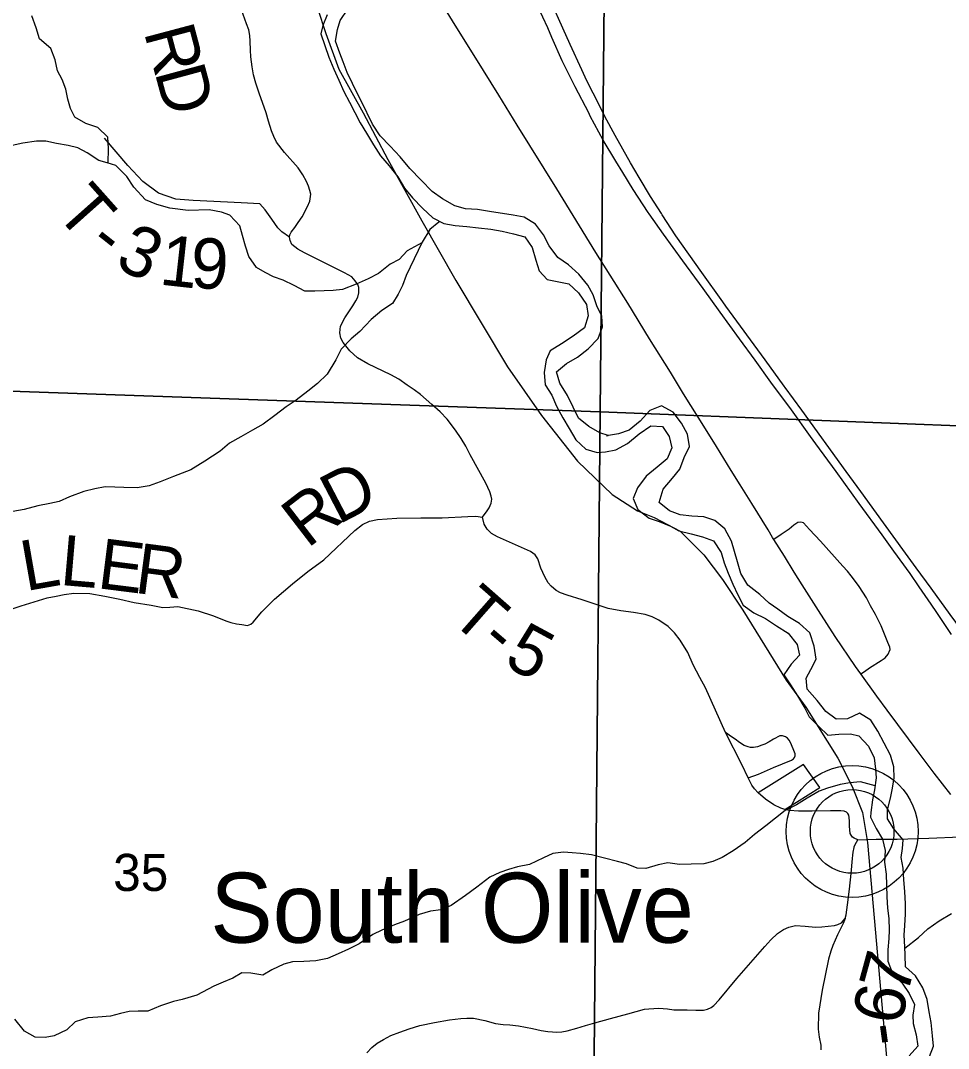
# Model space of a CAD drawing. Extents: x 0 to 34, y 0 to 22.
# Drawn here: x 2.91 to 3.957, y 19.001 to 20.162 of the extents above; entities that cross this region are included whole.
import ezdxf

# ---------------------------------------------------------------- set-up
doc = ezdxf.new("R2010")
doc.units = 0
for name, color, linetype in [('GM_X_County_Road', 7, 'Continuous'), ('GM_X_Interstate_Route', 7, 'Continuous'), ('GM_X_Major_River', 7, 'Continuous'), ('GM_X_Minor_River', 7, 'Continuous'), ('GM_X_Rail_Line', 7, 'Continuous'), ('GM_X_Section', 7, 'Continuous'), ('GM_X_Section_Text', 7, 'Continuous'), ('GM_X_State_Route', 7, 'Continuous'), ('GM_X_Township_Road', 7, 'Continuous'), ('GM_X_Township_Road_Text', 7, 'Continuous'), ('GM_X_Unincorporated', 7, 'Continuous'), ('GM_X_Unincorporated_Location', 7, 'Continuous'), ('GM_X_Unincorporated_Text', 7, 'Continuous')]:
    doc.layers.add(name, color=color, linetype=linetype)

msp = doc.modelspace()

# ---------------------------------------------------------------- linework, layer by layer
at = {"layer": 'GM_X_County_Road'}
msp.add_lwpolyline([(3.8547, 19.2369), (3.8754, 19.2377), (3.899, 19.2377), (3.9348, 19.2389), (3.9706, 19.2404), (3.9804, 19.2423), (3.9864, 19.2446), (3.9913, 19.2477)], dxfattribs=at)
at = {"layer": 'GM_X_Interstate_Route'}
for points in [[(3.634, 19.9423), (3.6329, 19.944), (3.6207, 19.9631), (3.6078, 19.9846), (3.5982, 20.0009), (3.5807, 20.0317), (3.5692, 20.0532), (3.5629, 20.0658), (3.5488, 20.0937), (3.5432, 20.1059), (3.5299, 20.1347), (3.5004, 20.2012)], [(3.6193, 19.9434), (3.6181, 19.945), (3.6011, 19.971), (3.5893, 19.9901), (3.5815, 20.003), (3.5674, 20.0265), (3.5527, 20.0537), (3.551, 20.0573), (3.5355, 20.0866), (3.5292, 20.0994), (3.5209, 20.1162), (3.5092, 20.1424), (3.5047, 20.1532), (3.4936, 20.1773)], [(3.9238, 19.5226), (3.9136, 19.5374), (3.8952, 19.5626), (3.882, 19.5811), (3.8561, 19.6167), (3.8301, 19.6525), (3.8074, 19.6839), (3.8013, 19.692), (3.7797, 19.7221), (3.7566, 19.7535), (3.7387, 19.7782), (3.7212, 19.8022), (3.6992, 19.8324), (3.68, 19.859), (3.657, 19.8905), (3.6354, 19.9204), (3.6193, 19.9434)], [(3.7022, 19.8441), (3.6785, 19.8771), (3.6494, 19.9188), (3.634, 19.9423)], [(3.7727, 19.7474), (3.7715, 19.749), (3.7499, 19.7786), (3.7057, 19.8393), (3.7022, 19.8441)], [(3.9374, 19.5209), (3.9206, 19.5438), (3.9056, 19.5646), (3.8758, 19.6055), (3.858, 19.6299), (3.8416, 19.6525), (3.7913, 19.7217), (3.7727, 19.7474)], [(3.9603, 19.4687), (3.9439, 19.4935), (3.9374, 19.5029), (3.9238, 19.5226)], [(4.4136, 19.002), (4.4082, 19.0064), (4.3656, 19.0403), (4.3133, 19.0822), (4.2605, 19.1242), (4.2222, 19.1561), (4.2043, 19.1721), (4.1931, 19.1833), (4.1764, 19.2002), (4.1626, 19.2155), (4.1424, 19.2399), (4.1299, 19.2562), (4.115, 19.2766), (4.0958, 19.3028), (4.085, 19.318), (4.0563, 19.3574), (4.0431, 19.3754), (4.0122, 19.4179), (3.9866, 19.4532), (3.9769, 19.4666), (3.9589, 19.4914), (3.9374, 19.5209)]]:
    msp.add_lwpolyline(points, dxfattribs=at)
at = {"layer": 'GM_X_Major_River'}
for points in [[(3.5728, 19.6934), (3.5633, 19.6963), (3.551, 19.7034), (3.5392, 19.7128), (3.5333, 19.7252), (3.5271, 19.7384), (3.5182, 19.7524), (3.5146, 19.7652), (3.5259, 19.7745), (3.5384, 19.7818), (3.5504, 19.7911), (3.5617, 19.8029), (3.5664, 19.8159), (3.5659, 19.828), (3.5601, 19.8397), (3.5558, 19.8522), (3.5499, 19.8631), (3.5399, 19.8755), (3.528, 19.8857), (3.5162, 19.8942), (3.5062, 19.9074), (3.4999, 19.9199), (3.4907, 19.9319), (3.4781, 19.9397), (3.4655, 19.9418), (3.4389, 19.9461), (3.4252, 19.9482), (3.4119, 19.9492), (3.3997, 19.9525), (3.3859, 19.9603), (3.3741, 19.9688), (3.3618, 19.9816), (3.3491, 19.9947), (3.3379, 20.0079), (3.3268, 20.0199), (3.3156, 20.0315), (3.3067, 20.0447), (3.2943, 20.0704), (3.2892, 20.0802), (3.2842, 20.0904), (3.2784, 20.1028), (3.2737, 20.1149), (3.2701, 20.1247), (3.265, 20.1383), (3.2672, 20.1516), (3.2705, 20.1616), (3.279, 20.1746)], [(3.2556, 20.1682), (3.2508, 20.156), (3.2486, 20.1465), (3.2576, 20.1204), (3.2631, 20.1068), (3.269, 20.0944), (3.2744, 20.0815), (3.281, 20.0695), (3.2931, 20.0461), (3.3, 20.0344), (3.3078, 20.0212), (3.3159, 20.0088), (3.3255, 19.9975), (3.3355, 19.9851), (3.3429, 19.9723), (3.3521, 19.9614), (3.3633, 19.9497), (3.3748, 19.9389), (3.3874, 19.9326), (3.4003, 19.9301), (3.4133, 19.9291), (3.4266, 19.9277), (3.4403, 19.926), (3.4532, 19.9239), (3.4661, 19.921), (3.4787, 19.9173), (3.4872, 19.9053), (3.4912, 19.8913), (3.4951, 19.8792), (3.5039, 19.8694), (3.5283, 19.8644), (3.5394, 19.8543), (3.5483, 19.8411), (3.5504, 19.8282), (3.5463, 19.8149), (3.5332, 19.8053), (3.5203, 19.7968), (3.5075, 19.7887), (3.5027, 19.7787), (3.5006, 19.7643), (3.5019, 19.7506), (3.5092, 19.7386), (3.5147, 19.7265), (3.5217, 19.7133), (3.5287, 19.7013), (3.5364, 19.6884), (3.5475, 19.678), (3.5605, 19.6739), (3.57, 19.6748), (3.5817, 19.6772), (3.5945, 19.6842), (3.6077, 19.695), (3.6209, 19.7042), (3.6342, 19.7033), (3.6419, 19.692), (3.6447, 19.6795), (3.6396, 19.6669), (3.6283, 19.6577), (3.6159, 19.6473), (3.6058, 19.6342), (3.601, 19.622), (3.6064, 19.6096), (3.6191, 19.5999)], [(3.9355, 18.9924), (3.94, 19.0042), (3.9391, 19.0156), (3.9374, 19.0308), (3.9353, 19.0429), (3.9329, 19.0569), (3.9282, 19.0697), (3.9197, 19.0833), (3.9086, 19.0934), (3.908, 19.1067), (3.9079, 19.1162), (3.907, 19.1294), (3.9076, 19.1404), (3.9086, 19.153), (3.9085, 19.1647), (3.9079, 19.1787), (3.9067, 19.1916), (3.9057, 19.2049), (3.9037, 19.217), (3.9051, 19.2273), (3.9058, 19.2368), (3.8954, 19.2495), (3.888, 19.2608), (3.8883, 19.2707), (3.8915, 19.284), (3.8933, 19.2935), (3.8958, 19.3064), (3.8953, 19.3193), (3.8917, 19.3326), (3.8844, 19.3461), (3.8774, 19.3597), (3.8693, 19.3721), (3.8566, 19.38), (3.843, 19.3734), (3.8301, 19.3732), (3.8186, 19.3818), (3.8086, 19.3942), (3.7975, 19.407), (3.7962, 19.4195), (3.8018, 19.429), (3.8077, 19.4408), (3.8053, 19.4556), (3.8005, 19.4704), (3.789, 19.4812), (3.7756, 19.489), (3.7642, 19.4972), (3.7546, 19.504), (3.7442, 19.5137), (3.7304, 19.5245), (3.7227, 19.5374), (3.7187, 19.5506), (3.7156, 19.5623), (3.712, 19.574), (3.7046, 19.588), (3.6931, 19.5973), (3.6809, 19.6014), (3.6673, 19.6023), (3.6543, 19.6037), (3.6421, 19.6081), (3.6306, 19.6178), (3.635, 19.6327), (3.6455, 19.645), (3.6537, 19.6553), (3.6585, 19.6683), (3.6648, 19.6808), (3.6624, 19.6949), (3.6558, 19.7073), (3.6462, 19.7197), (3.6332, 19.7268), (3.6199, 19.7213), (3.6091, 19.7094), (3.5967, 19.6994), (3.5846, 19.6951), (3.5709, 19.693), (3.5728, 19.6934)], [(3.6191, 19.5999), (3.6305, 19.5962), (3.6431, 19.591), (3.6526, 19.5858), (3.6664, 19.5822), (3.6793, 19.579), (3.6919, 19.5742), (3.7004, 19.5614), (3.7039, 19.5497), (3.7083, 19.5379), (3.7137, 19.5255), (3.7192, 19.5134), (3.7254, 19.5017), (3.7372, 19.4931), (3.7506, 19.4868), (3.7629, 19.4786), (3.7759, 19.4701), (3.7863, 19.4573), (3.7887, 19.4452), (3.7793, 19.4352), (3.7711, 19.4233), (3.7788, 19.4117), (3.7865, 19.3996), (3.7947, 19.3857), (3.7997, 19.3759), (3.8105, 19.365), (3.8209, 19.3549), (3.8334, 19.3562), (3.8463, 19.3567), (3.8558, 19.3542), (3.8666, 19.3425), (3.8732, 19.3293), (3.8748, 19.3168), (3.8753, 19.307), (3.8736, 19.2933), (3.8711, 19.2819), (3.8693, 19.2678)], [(3.8693, 19.2678), (3.869, 19.2625), (3.8752, 19.2497), (3.8826, 19.2376), (3.8854, 19.2248), (3.8848, 19.2119), (3.8865, 19.1982), (3.887, 19.1857), (3.8875, 19.1724), (3.888, 19.1599), (3.8897, 19.1482), (3.8899, 19.1349), (3.8896, 19.1254), (3.8886, 19.1129), (3.8884, 19.1), (3.8934, 19.0872), (3.9046, 19.0751), (3.9127, 19.0635), (3.9185, 19.051), (3.9168, 19.0392), (3.9173, 19.0298), (3.9205, 19.0169), (3.9225, 19.004), (3.9128, 18.9933)]]:
    msp.add_lwpolyline(points, dxfattribs=at)
at = {"layer": 'GM_X_Minor_River'}
for points in [[(3.0085, 20.0007), (3.0089, 20.0173), (3.008, 20.0298), (2.997, 20.0407), (2.9833, 20.0455), (2.9707, 20.0526), (2.9661, 20.0625), (2.963, 20.0727), (2.9606, 20.084), (2.9567, 20.095), (2.9514, 20.1048), (2.9486, 20.1173), (2.9436, 20.1301), (2.931, 20.141), (2.9271, 20.1535), (2.9224, 20.1668)], [(3.0987, 19.9472), (3.078, 19.9497), (3.0636, 19.9541), (3.0507, 19.9593), (3.0373, 19.9736), (3.0296, 19.9856), (3.017, 19.998), (3.0075, 20.001), (2.9981, 20.0036), (2.9847, 20.0122), (2.9741, 20.0178), (2.9635, 20.0207), (2.9502, 20.0229), (2.9381, 20.0254), (2.9275, 20.0253), (2.912, 20.0233), (2.9002, 20.0205)], [(3.3624, 19.9107), (3.3458, 19.9015), (3.3371, 19.8919), (3.3269, 19.8866), (3.3137, 19.8762), (3.3019, 19.8701), (3.2883, 19.8639), (3.2731, 19.8581), (3.2625, 19.8569), (3.2523, 19.8565), (3.2416, 19.856), (3.2306, 19.856), (3.2184, 19.8627), (3.2062, 19.8687), (3.1952, 19.8724), (3.1857, 19.8773), (3.1758, 19.8829), (3.1673, 19.8954), (3.1635, 19.9071), (3.16, 19.9189), (3.1572, 19.9298), (3.1458, 19.9419), (3.1363, 19.9453), (3.1226, 19.9478), (3.0987, 19.9472)], [(3.3833, 19.9346), (3.3816, 19.934), (3.3714, 19.9259), (3.3628, 19.9115), (3.3583, 19.9019), (3.3448, 19.8738), (3.3407, 19.8627), (3.3358, 19.8528), (3.3294, 19.8422), (3.3173, 19.8345), (3.3053, 19.8242), (3.2924, 19.8108), (3.2826, 19.8024), (3.2713, 19.7906), (3.2653, 19.7788), (3.2555, 19.7624), (3.2446, 19.7521), (3.234, 19.7433), (3.2208, 19.7333), (3.2095, 19.7257), (3.1966, 19.7157), (3.1834, 19.7062), (3.1713, 19.6992), (3.1581, 19.6919), (3.1456, 19.6847), (3.135, 19.6755), (3.1176, 19.6644), (3.1019, 19.6545)], [(3.1019, 19.6545), (3.0822, 19.6471), (3.0671, 19.6409), (3.0547, 19.6366), (3.0414, 19.6342), (3.0263, 19.6345), (3.0161, 19.6348), (3.0051, 19.6354), (2.9934, 19.6331), (2.9809, 19.6299), (2.9647, 19.6241), (2.953, 19.6187), (2.9428, 19.6167), (2.9292, 19.6139), (2.9137, 19.6096), (2.9009, 19.6076)], [(3.8742, 19.2979), (3.8577, 19.3023), (3.8456, 19.3011), (3.8346, 19.2992), (3.8206, 19.2953), (3.8111, 19.2918), (3.7975, 19.2841), (3.7854, 19.2765), (3.7725, 19.2699), (3.7619, 19.2615), (3.751, 19.2527), (3.7381, 19.2431), (3.7276, 19.234), (3.714, 19.2244), (3.7015, 19.2171), (3.6909, 19.2125), (3.6807, 19.2098), (3.6666, 19.2093), (3.6533, 19.2092), (3.6404, 19.211), (3.6294, 19.2087), (3.6154, 19.2044), (3.6055, 19.2051), (3.5937, 19.21), (3.5834, 19.2125), (3.5686, 19.2162), (3.5541, 19.2199), (3.5416, 19.2214), (3.5321, 19.2224), (3.5226, 19.2231), (3.5105, 19.2215), (3.4999, 19.2165), (3.484, 19.2092), (3.4707, 19.2065), (3.4605, 19.2034), (3.4506, 19.1999), (3.4393, 19.1949), (3.4245, 19.1834), (3.4117, 19.1742), (3.3958, 19.1628), (3.3841, 19.1581), (3.3723, 19.1565), (3.3594, 19.1527), (3.3431, 19.1453), (3.3318, 19.1411), (3.3174, 19.1349), (3.3072, 19.1299), (3.2917, 19.1196), (3.2799, 19.1135), (3.2682, 19.1081), (3.2561, 19.1031), (3.2428, 19.1003), (3.2292, 19.0995), (3.2166, 19.0994), (3.2068, 19.0967), (3.1932, 19.0901), (3.1829, 19.084), (3.1696, 19.0866), (3.1594, 19.0869), (3.1492, 19.0807), (3.1382, 19.0761), (3.1276, 19.0719), (3.1085, 19.0616)], [(3.9079, 19.1145), (3.9231, 19.1268), (3.9336, 19.1363), (3.9465, 19.1455), (3.9605, 19.1536)], [(3.1085, 19.0616), (3.092, 19.0569), (3.0821, 19.0545), (3.0674, 19.0495), (3.0531, 19.0437), (3.0425, 19.0436), (3.0323, 19.0431), (3.0225, 19.0411), (3.0111, 19.038), (2.9968, 19.0367), (2.9854, 19.0362), (2.9714, 19.0316), (2.9617, 19.0224), (2.9477, 19.0158), (2.9372, 19.0138), (2.9262, 19.0141), (2.914, 19.0208), (2.9033, 19.0344)]]:
    msp.add_lwpolyline(points, dxfattribs=at)
at = {"layer": 'GM_X_Rail_Line'}
msp.add_lwpolyline([(3.2446, 20.1754), (3.2542, 20.147), (3.2689, 20.1068), (3.2962, 20.0573), (3.3242, 20.0048), (3.3626, 19.9354), (3.401, 19.8682), (3.4593, 19.7707), (3.4977, 19.716), (3.5383, 19.6643), (3.5774, 19.6267), (3.6061, 19.6082), (3.6246, 19.6008), (3.6541, 19.5853), (3.6808, 19.5586), (3.7021, 19.5306), (3.725, 19.4962), (3.7739, 19.417), (3.796, 19.3867), (3.832, 19.329), (3.8482, 19.2973), (3.8599, 19.2677), (3.8655, 19.2339), (3.8882, 18.9789)], dxfattribs=at)
at = {"layer": 'GM_X_Section'}
for points in [[(2.5664, 20.7581), (3.5738, 20.7275), (3.5637, 19.7201), (2.5439, 19.7556)], [(4.5766, 20.6934), (4.5761, 20.6339), (4.5646, 19.6808), (3.5637, 19.7201), (3.5738, 20.7275)], [(2.5439, 19.7556), (3.5637, 19.7201), (3.5541, 18.6711), (2.551, 18.706), (2.5214, 18.7068)], [(4.5646, 19.6808), (4.5644, 19.6379), (4.5473, 18.6426), (3.5541, 18.6711), (3.5637, 19.7201)]]:
    msp.add_lwpolyline(points, close=True, dxfattribs=at)
at = {"layer": 'GM_X_State_Route'}
msp.add_lwpolyline([(3.9598, 19.288), (3.941, 19.3122), (3.9238, 19.3349), (3.8876, 19.3831), (3.876, 19.3989), (3.8582, 19.4243), (3.852, 19.4325), (3.8292, 19.4664), (3.8102, 19.4956), (3.7918, 19.5246), (3.7829, 19.5389), (3.7718, 19.5571), (3.76, 19.5758), (3.7584, 19.5783), (3.7533, 19.5868), (3.735, 19.6164), (3.7218, 19.6376), (3.7116, 19.6539), (3.695, 19.6807), (3.6827, 19.7009), (3.6579, 19.7403), (3.6431, 19.7648), (3.6197, 19.8024), (3.595, 19.8425), (3.5753, 19.8742), (3.5591, 19.8998), (3.5149, 19.9717), (3.47, 20.0435), (3.4493, 20.0772), (3.4234, 20.1192), (3.4002, 20.1565), (3.3881, 20.176)], dxfattribs=at)
at = {"layer": 'GM_X_Township_Road'}
for points in [[(3.6225, 19.4885), (3.6145, 19.4912), (3.6015, 19.4935), (3.5871, 19.4953), (3.5729, 19.4981), (3.5434, 19.5077), (3.5267, 19.513), (3.5192, 19.5157), (3.5142, 19.5185), (3.5085, 19.5231), (3.5052, 19.5271), (3.5013, 19.5338), (3.4968, 19.5437), (3.4933, 19.5539), (3.4905, 19.5585), (3.4852, 19.5622), (3.448, 19.5789), (3.441, 19.5828), (3.4361, 19.5877), (3.4329, 19.5932), (3.4311, 19.6011), (3.4364, 19.6083), (3.4385, 19.6116), (3.4409, 19.6168), (3.4415, 19.6213), (3.4408, 19.6249), (3.4393, 19.6297), (3.4346, 19.6393), (3.4172, 19.6713), (3.4121, 19.6814), (3.4071, 19.6899), (3.4007, 19.6994), (3.3911, 19.7116), (3.3831, 19.7198), (3.3739, 19.7284), (3.3609, 19.7395), (3.354, 19.7449), (3.3461, 19.75), (3.3364, 19.7567), (3.3274, 19.7618), (3.3014, 19.774), (3.2899, 19.7811), (3.2812, 19.7889), (3.2739, 19.7984), (3.2711, 19.8032), (3.2698, 19.8091), (3.2707, 19.8168), (3.2756, 19.8259), (3.2847, 19.8396), (3.2882, 19.8452), (3.2902, 19.8495), (3.2915, 19.8543), (3.2914, 19.8604), (3.2904, 19.8637), (3.2874, 19.868), (3.2834, 19.8723), (3.2754, 19.8768), (3.2646, 19.8823), (3.2525, 19.8882), (3.23, 19.8995), (3.2224, 19.9034), (3.2159, 19.9087), (3.2138, 19.9133), (3.2131, 19.9172), (3.2134, 19.9199), (3.2149, 19.9227), (3.2191, 19.9281), (3.223, 19.9335), (3.2273, 19.9402), (3.2335, 19.9519), (3.2362, 19.9579), (3.2371, 19.9658), (3.2362, 19.9699), (3.2347, 19.9748), (3.2325, 19.98), (3.2284, 19.9876), (3.223, 19.9955), (3.2077, 20.0125), (3.1984, 20.0242), (3.1953, 20.0308), (3.1929, 20.037), (3.1896, 20.0481), (3.1869, 20.0573), (3.1789, 20.0796), (3.1753, 20.0909), (3.1726, 20.1003), (3.1709, 20.1094), (3.1694, 20.1208), (3.1692, 20.128), (3.1689, 20.1383), (3.1685, 20.1449), (3.1673, 20.1511), (3.1648, 20.1579), (3.1589, 20.1737)], [(3.2131, 19.9172), (3.2044, 19.923), (3.2, 19.9277), (3.1933, 19.9375), (3.1858, 19.9481), (3.1797, 19.9546), (3.1585, 19.956), (3.1046, 19.9585), (3.0849, 19.9599), (3.0652, 19.9667), (3.0477, 19.9799), (3.0306, 19.9981), (3.0043, 20.0287)], [(2.8892, 19.4938), (2.9104, 19.5011), (2.9396, 19.5099), (2.9499, 19.5121), (2.959, 19.5139), (2.9699, 19.5154), (2.9877, 19.515), (3.0046, 19.5118), (3.0215, 19.5086), (3.0377, 19.5049), (3.0572, 19.5016), (3.0701, 19.4993), (3.078, 19.4995), (3.0871, 19.5001), (3.1101, 19.4953), (3.1275, 19.4899), (3.1413, 19.4842), (3.1471, 19.4821), (3.1534, 19.4806), (3.1593, 19.4798), (3.1657, 19.479), (3.1695, 19.4804), (3.172, 19.4824), (3.1821, 19.4944), (3.1963, 19.5084), (3.2164, 19.5259), (3.234, 19.5397), (3.2518, 19.5529), (3.2869, 19.5859), (3.2955, 19.5927), (3.3036, 19.5966), (3.3125, 19.5983), (3.3344, 19.6), (3.3613, 19.6004), (3.3855, 19.6004), (3.4145, 19.6017), (3.4236, 19.6021), (3.4311, 19.6011)], [(3.8001, 19.5873), (3.7933, 19.5947), (3.7904, 19.5956), (3.7871, 19.5952), (3.7824, 19.5919), (3.777, 19.5877), (3.7683, 19.5814), (3.76, 19.5758)], [(3.8897, 19.4482), (3.8901, 19.4491), (3.891, 19.4519), (3.8908, 19.4544), (3.8887, 19.4598), (3.881, 19.4784), (3.8748, 19.4911), (3.8691, 19.5012), (3.8643, 19.5101), (3.8562, 19.5229), (3.8521, 19.5284), (3.8473, 19.5348), (3.843, 19.5401), (3.8379, 19.5459), (3.8125, 19.5739), (3.8001, 19.5873)], [(3.7722, 19.2712), (3.7677, 19.2726), (3.76, 19.2764), (3.7503, 19.2828), (3.742, 19.2898), (3.7381, 19.2945), (3.7351, 19.2988), (3.731, 19.307), (3.7237, 19.322), (3.7052, 19.358), (3.6829, 19.4086), (3.6763, 19.4201), (3.6689, 19.4346), (3.6627, 19.4483), (3.6542, 19.4621), (3.6479, 19.4706), (3.6405, 19.4778), (3.6302, 19.485), (3.6225, 19.4885)], [(3.8582, 19.4243), (3.8621, 19.427), (3.868, 19.4309), (3.8811, 19.4394), (3.8855, 19.4424), (3.8889, 19.4465), (3.8897, 19.4482)], [(3.731, 19.307), (3.7424, 19.3112), (3.7595, 19.3185), (3.7798, 19.3269), (3.7819, 19.3283), (3.7832, 19.3299), (3.784, 19.3317), (3.7838, 19.3341), (3.7816, 19.3397), (3.7787, 19.3469), (3.7771, 19.3495), (3.7751, 19.3518), (3.7729, 19.3533), (3.7696, 19.3544), (3.7668, 19.3543), (3.7596, 19.3505), (3.7547, 19.3476), (3.7496, 19.3449), (3.7462, 19.3436), (3.7413, 19.342), (3.7369, 19.3411), (3.7337, 19.3411), (3.7308, 19.3419), (3.7264, 19.3435), (3.7211, 19.3469), (3.7161, 19.3507), (3.7122, 19.3533), (3.7052, 19.358)], [(3.7722, 19.2712), (3.8119, 19.296), (3.7935, 19.3218), (3.742, 19.2898)], [(3.8507, 19.2291), (3.8515, 19.2315), (3.8547, 19.2369), (3.8505, 19.2388), (3.8486, 19.24), (3.8471, 19.242), (3.8459, 19.2442), (3.8451, 19.2525), (3.8451, 19.2579), (3.8448, 19.2622), (3.8444, 19.2647), (3.8435, 19.2666), (3.8417, 19.2682), (3.8393, 19.2692), (3.8355, 19.2697), (3.8237, 19.2697), (3.8033, 19.2693), (3.7876, 19.2691), (3.7776, 19.27), (3.7722, 19.2712)], [(3.3003, 18.9964), (3.3062, 19.0024), (3.312, 19.0074), (3.3191, 19.0117), (3.3274, 19.0161), (3.3376, 19.0198), (3.3481, 19.0235), (3.3603, 19.0272), (3.3768, 19.0307), (3.3936, 19.0338), (3.4064, 19.0354), (3.4134, 19.0357), (3.4208, 19.0355), (3.4335, 19.0329), (3.4456, 19.0296), (3.4543, 19.0284), (3.462, 19.028), (3.4716, 19.027), (3.4876, 19.0241), (3.4973, 19.0218), (3.5046, 19.0207), (3.5101, 19.0201), (3.5147, 19.0198), (3.5206, 19.0202), (3.5264, 19.0214), (3.5374, 19.0245), (3.5471, 19.0274), (3.5578, 19.0302), (3.5756, 19.0352), (3.595, 19.0406), (3.6139, 19.0457), (3.6188, 19.0463), (3.6302, 19.0469), (3.6399, 19.046), (3.6469, 19.0452), (3.6619, 19.045), (3.6719, 19.0446), (3.6805, 19.0446), (3.6851, 19.0457), (3.689, 19.0476), (3.6921, 19.05), (3.6983, 19.0563), (3.7182, 19.0806), (3.7498, 19.1166), (3.7565, 19.1239), (3.7641, 19.1313), (3.7707, 19.1359), (3.7767, 19.1385), (3.7842, 19.1402), (3.7953, 19.1393), (3.807, 19.1385), (3.8141, 19.1386), (3.8213, 19.1393), (3.8284, 19.1404), (3.832, 19.1412), (3.8361, 19.1433), (3.8404, 19.1483), (3.8414, 19.1521), (3.8429, 19.1636), (3.8453, 19.1811), (3.8472, 19.199), (3.8486, 19.2159), (3.8489, 19.2198), (3.8494, 19.223), (3.8505, 19.2283), (3.8507, 19.2291)], [(3.8404, 19.1483), (3.8383, 19.1426), (3.8316, 19.1297), (3.8265, 19.1176), (3.8241, 19.1112), (3.8216, 19.1023), (3.8145, 19.0674), (3.8104, 19.0414), (3.81, 19.0231), (3.8111, 19.0142), (3.8129, 19.0052), (3.8131, 19)]]:
    msp.add_lwpolyline(points, dxfattribs=at)
at = {"layer": 'GM_X_Unincorporated'}
for radius in [0.0744, 0.0472]:
    msp.add_circle((3.8483, 19.2464), radius, dxfattribs=at)
at = {"layer": 'GM_X_Unincorporated_Location'}
msp.add_line((3.8483, 19.2464), (3.8483, 19.2464), dxfattribs=at)

# ---------------------------------------------------------------- texts
at = {"layer": 'GM_X_Section_Text'}
msp.add_text('35', height=0.04186, rotation=0, dxfattribs=at).set_placement((3.0141, 19.1792))
at = {"layer": 'GM_X_Township_Road_Text'}
for s, rotation, p in [('R', 284.8693, (3.0486, 20.1489)), ('D', 285.1347, (3.0607, 20.1035)), ('T', 311.6496, (2.9472, 19.9448)), ('-', 321.6794, (2.9834, 19.9057)), ('3', 335.5869, (3.0145, 19.8834)), ('1', 353.6978, (3.0652, 19.8638)), ('9', 357.7044, (3.101, 19.8598)), ('D', 27.5344, (3.2681, 19.5922)), ('R', 37.5857, (3.2333, 19.5651)), ('L', 9.9844, (2.9153, 19.5175)), ('L', 355.0655, (2.9532, 19.5247)), ('E', 352.8548, (2.995, 19.5211)), ('R', 352.4848, (3.0371, 19.5159)), ('T', 318.6814, (3.3925, 19.4859)), ('5', 331.6842, (3.4534, 19.4348)), ('-', 319.4754, (3.425, 19.4573)), ('7', 74.6636, (3.91, 19.0597)), ('6', 80.1313, (3.9043, 19.0266)), ('-', 97.8258, (3.9076, 19.0081))]:
    msp.add_text(s, height=0.0568, rotation=rotation, dxfattribs=at).set_placement(p)
at = {"layer": 'GM_X_Unincorporated_Text'}
msp.add_text('South Olive', height=0.078977, rotation=0, dxfattribs=at).set_placement((3.1237, 19.1208))

doc.saveas('drawing.dxf')
